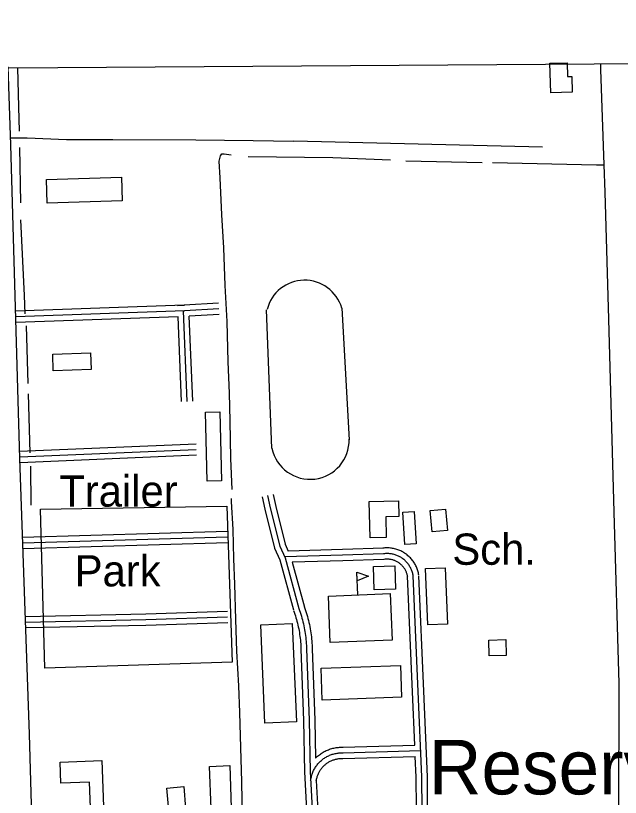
# Model space of a CAD drawing. Extents: x 3508733 to 3546731, y 546897 to 572481.
# Drawn here: x 3524097 to 3525704, y 568617 to 570695 of the extents above; entities that cross this region are included whole.
import ezdxf

# ---------------------------------------------------------------- set-up
doc = ezdxf.new("R2010")
doc.units = 0
for name, color, linetype in [('V-BLDG-IDEN', 7, 'Continuous'), ('V-BLDG-OTLN', 7, 'Continuous'), ('V-DTCH-CNTR', 7, 'Continuous'), ('V-GRID-FRAM', 7, 'Continuous'), ('V-ROAD-CNTR', 7, 'Continuous'), ('V-TOPO-GNAM-IDEN', 7, 'Continuous'), ('V-TOPO-SHOR', 7, 'Continuous')]:
    doc.layers.add(name, color=color, linetype=linetype)

msp = doc.modelspace()

# ---------------------------------------------------------------- linework, layer by layer
at = {"layer": 'V-BLDG-IDEN'}
msp.add_lwpolyline([(3524163, 569383.4), (3524658, 569391.5), (3524672.6, 568976.8), (3524174.1, 568960.4)], close=True, dxfattribs=at)
at = {"layer": 'V-BLDG-OTLN'}
for p, q in [((3525516.2, 570569), (3525562.5, 570569.3)), ((3525006.2, 569155.9), (3525003.7, 569215.9))]:
    msp.add_line(p, q, dxfattribs=at)
for points in [[(3525518.7, 570489.7), (3525516.2, 570569)], [(3525562.5, 570569.3), (3525563.6, 570533.3), (3525574.8, 570533.7), (3525576.1, 570491.5), (3525518.7, 570489.7)], [(3524778, 569545.1), (3524763.3, 569912.8)], [(3524963.5, 569917.9), (3524983, 569567.8)]]:
    msp.add_lwpolyline(points, dxfattribs=at)
for points in [[(3524379.8, 570203.1), (3524180.4, 570196.8), (3524178.4, 570259.5), (3524377.8, 570265.8)], [(3524297.4, 569754.5), (3524196.8, 569751.4), (3524195.4, 569795.5), (3524296, 569798.6)], [(3524639.5, 569641.7), (3524643.8, 569458.9), (3524605.7, 569458.1), (3524601.4, 569640.8)], [(3525038.7, 569307.2), (3525036.2, 569403.4), (3525114.4, 569405.5), (3525115.5, 569364.2), (3525080.4, 569363.3), (3525081.8, 569308.4)], [(3525155.8, 569377.4), (3525160.9, 569291.4), (3525130.9, 569289.6), (3525125.8, 569375.6)], [(3525203.3, 569323.3), (3525198.4, 569379.7), (3525239.4, 569383.3), (3525244.3, 569326.9)], [(3525106.4, 569170.8), (3525049.7, 569169), (3525047.7, 569231.2), (3525104.4, 569233)], [(3525192.2, 569076.1), (3525186.3, 569225.5), (3525238.6, 569227.6), (3525244.5, 569078.2)], [(3525003.7, 569215.9), (3525034.2, 569205.6), (3525004.7, 569192.8)], [(3525097.7, 569035.5), (3524933, 569028.7), (3524927.8, 569152.6), (3525092.5, 569159.5)], [(3524759.1, 568814.4), (3524748.2, 569076.4), (3524832, 569079.9), (3524842.9, 568817.9)], [(3525400.4, 568994.7), (3525355.4, 568993.2), (3525354, 569035.4), (3525399.1, 569036.8)], [(3525122.4, 568883.3), (3524911.4, 568875.7), (3524908.4, 568960.5), (3525119.3, 568968.1)], [(3524215.3, 568711.4), (3524326, 568715.4), (3524331.3, 568568.6), (3524296.7, 568567.4), (3524293.5, 568657.9), (3524217.3, 568655.1)], [(3524616.6, 568588), (3524612.4, 568699.7), (3524665.7, 568701.7), (3524669.9, 568590)], [(3524503.8, 568583.7), (3524498.5, 568642), (3524543.4, 568646), (3524548.6, 568587.8)]]:
    msp.add_lwpolyline(points, close=True, dxfattribs=at)
for centre, radius, start, end in [((3524864.8, 569889.2), 102.8, 16.2577, 165.9891), ((3524879.5, 569566.3), 103.6, 191.783, 1.8986)]:
    msp.add_arc(centre, radius, start, end, dxfattribs=at)
at = {"layer": 'V-DTCH-CNTR'}
msp.add_line((3525497.1, 570345.5), (3524836, 570361.2), dxfattribs=at)
msp.add_lwpolyline([(3524081.6, 570370.2), (3524127.3, 570369.9), (3524231.6, 570366.1), (3524355.4, 570366.3), (3524575.5, 570364.9), (3524727.8, 570362.8), (3524836, 570361.2)], dxfattribs=at)
at = {"layer": 'V-GRID-FRAM'}
msp.add_lwpolyline([(3512800, 570478.9), (3544431.3, 570695.1), (3544563.5, 552512.4), (3512916.4, 552296.1), (3512800, 570478.9)], dxfattribs=at)
at = {"layer": 'V-ROAD-CNTR'}
for points in [[(3524203.5, 566496.1), (3524208.2, 566552.7), (3524190.9, 567116.5), (3524174.8, 567625.9), (3524145.5, 568379.4), (3524133.2, 568785), (3524107.9, 569518.2), (3524083.6, 570351.6), (3524076.6, 570559.1)], [(3524636.3, 569930.6), (3524544.9, 569925.3), (3524096.4, 569909.9)], [(3524637.1, 569915.6), (3524545.6, 569910.3), (3524096.9, 569894.9)], [(3524527.1, 569924.7), (3524545.2, 569925.3)], [(3524552.7, 569670), (3524542.7, 569910.2), (3524545.6, 569910.3)], [(3524528.3, 569894.7), (3524097.4, 569879.9)], [(3524537.7, 569669.3), (3524528.3, 569894.7)], [(3524638, 569900.6), (3524558.3, 569896)], [(3524567.7, 569670.6), (3524558.3, 569896)], [(3524576.3, 569556.5), (3524107.2, 569536.6)], [(3524576.9, 569541.5), (3524107.8, 569521.6)], [(3524577.5, 569526.5), (3524108.5, 569506.6)], [(3524751.6, 569416.5), (3524758.7, 569383.5), (3524784.6, 569280.1), (3524799, 569248.7), (3524835.2, 569115.5)], [(3524766.2, 569419.6), (3524773.3, 569386.9), (3524798.9, 569285.1), (3524813.2, 569253.8), (3524849.7, 569119.4)], [(3524780.9, 569422.8), (3524787.9, 569390.3), (3524813.1, 569290.1), (3524821.3, 569272)], [(3524115.2, 569309.3), (3524659.6, 569324.9)], [(3524115.6, 569294.3), (3524660, 569309.9)], [(3524116.1, 569279.3), (3524660.4, 569294.9)], [(3525074.5, 569264.7), (3524965.5, 569261.3), (3524812.4, 569256.8), (3524813.2, 569253.8)], [(3525074, 569279.7), (3524965, 569276.3), (3524821.3, 569272)], [(3525168.2, 569208.4), (3525167.8, 569211), (3525167.2, 569213.8), (3525166.5, 569216.6), (3525165.8, 569219.3), (3525164.9, 569222.1), (3525164, 569224.8), (3525162.9, 569227.5), (3525161.8, 569230.1), (3525160.5, 569232.7), (3525159.2, 569235.3), (3525157.8, 569237.8), (3525156.4, 569240.3), (3525154.8, 569242.7), (3525153.1, 569245), (3525151.4, 569247.3), (3525149.6, 569249.6), (3525147.8, 569251.8), (3525145.8, 569253.9), (3525143.8, 569255.9), (3525141.7, 569257.9), (3525139.5, 569259.8), (3525137.3, 569261.7), (3525135.1, 569263.4), (3525132.7, 569265.1), (3525130.3, 569266.7), (3525127.9, 569268.2), (3525125.4, 569269.7), (3525122.9, 569271), (3525120.3, 569272.3), (3525117.7, 569273.5), (3525115, 569274.5), (3525112.3, 569275.5), (3525109.6, 569276.5), (3525106.8, 569277.3), (3525104, 569278), (3525101.2, 569278.6), (3525098.4, 569279.1), (3525095.6, 569279.6), (3525092.7, 569279.9), (3525089.8, 569280.2), (3525087, 569280.3), (3525084.1, 569280.4), (3525081.2, 569280.3), (3525078.3, 569280.2), (3525075.5, 569279.9), (3525072.7, 569279.6), (3525072.4, 569279.6)], [(3525153.5, 569205.8), (3525153.1, 569208.2), (3525152.6, 569210.5), (3525152, 569212.8), (3525151.4, 569215.1), (3525150.7, 569217.3), (3525149.9, 569219.6), (3525149, 569221.8), (3525148.1, 569224), (3525147.1, 569226.1), (3525146, 569228.2), (3525144.8, 569230.3), (3525143.6, 569232.3), (3525142.3, 569234.3), (3525141, 569236.3), (3525139.6, 569238.2), (3525138.1, 569240), (3525136.5, 569241.8), (3525134.9, 569243.5), (3525133.3, 569245.2), (3525131.6, 569246.9), (3525129.8, 569248.4), (3525128, 569249.9), (3525126.1, 569251.4), (3525124.2, 569252.8), (3525122.2, 569254.1), (3525120.2, 569255.4), (3525118.1, 569256.5), (3525116, 569257.7), (3525113.9, 569258.7), (3525111.7, 569259.7), (3525109.6, 569260.6), (3525107.3, 569261.4), (3525105.1, 569262.1), (3525102.8, 569262.8), (3525100.5, 569263.4), (3525098.2, 569263.9), (3525095.9, 569264.4), (3525093.5, 569264.7), (3525091.2, 569265), (3525088.8, 569265.2), (3525086.5, 569265.3), (3525084.1, 569265.4), (3525081.7, 569265.3), (3525079.3, 569265.2), (3525077, 569265), (3525074.6, 569264.7), (3525074.5, 569264.7)], [(3525075, 569249.7), (3524965.9, 569246.3), (3524831.8, 569242.3)], [(3524831.8, 569242.3), (3524864.1, 569123.3)], [(3525138.7, 569203.3), (3525138.3, 569205.4), (3525137.9, 569207.2), (3525137.5, 569209), (3525137, 569210.8), (3525136.4, 569212.6), (3525135.8, 569214.4), (3525135.1, 569216.1), (3525134.4, 569217.8), (3525133.6, 569219.5), (3525132.8, 569221.2), (3525131.9, 569222.8), (3525130.9, 569224.4), (3525129.9, 569225.9), (3525128.8, 569227.5), (3525127.7, 569229), (3525126.5, 569230.4), (3525125.3, 569231.8), (3525124.1, 569233.2), (3525122.8, 569234.5), (3525121.4, 569235.8), (3525120, 569237.1), (3525118.6, 569238.2), (3525117.1, 569239.4), (3525115.6, 569240.5), (3525114, 569241.5), (3525112.5, 569242.5), (3525110.8, 569243.4), (3525109.2, 569244.3), (3525107.5, 569245.1), (3525105.8, 569245.9), (3525104.1, 569246.6), (3525102.4, 569247.2), (3525100.6, 569247.8), (3525098.8, 569248.4), (3525097, 569248.8), (3525095.2, 569249.2), (3525093.4, 569249.6), (3525091.5, 569249.9), (3525089.7, 569250.1), (3525087.8, 569250.2), (3525085.9, 569250.3), (3525084.1, 569250.4), (3525082.2, 569250.3), (3525080.4, 569250.2), (3525078.5, 569250.1), (3525076.5, 569249.8), (3525076.5, 569249.8)], [(3525157.5, 568756.4), (3525151.8, 568898.2), (3525138.5, 569205.2)], [(3525177.8, 568494.3), (3525175.9, 568671.8), (3525166.8, 568898.8), (3525153.5, 569205.8)], [(3525192.6, 568510.3), (3525190.9, 568672.2), (3525181.8, 568899.4), (3525168.4, 569206.5)], [(3524849.7, 569119.4), (3524851.4, 569114.4), (3524853.1, 569109.4), (3524854.7, 569104.3), (3524856.2, 569099.2), (3524857.6, 569094.1), (3524859, 569089), (3524860.3, 569083.9), (3524861.5, 569078.7), (3524862.6, 569073.5), (3524863.7, 569068.3), (3524864.7, 569063.1), (3524865.6, 569057.9), (3524866.4, 569052.7), (3524867.1, 569047.4), (3524867.8, 569042.2), (3524868.4, 569036.9), (3524868.9, 569031.6), (3524869.3, 569026.3), (3524869.6, 569021), (3524869.9, 569015.7), (3524870, 569011.9)], [(3524863.8, 569124.3), (3524865.6, 569119.2), (3524867.4, 569114), (3524869, 569108.7), (3524870.6, 569103.4), (3524872.1, 569098.1), (3524873.5, 569092.8), (3524874.9, 569087.4), (3524876.1, 569082), (3524877.3, 569076.6), (3524878.4, 569071.2), (3524879.4, 569065.8), (3524880.4, 569060.3), (3524881.2, 569054.9), (3524882, 569049.4), (3524882.7, 569043.9), (3524883.3, 569038.4), (3524883.8, 569032.9), (3524884.2, 569027.4), (3524884.6, 569021.9), (3524884.9, 569016.4), (3524885, 569012.4)], [(3524122.6, 569098.5), (3524442.4, 569105.5), (3524659.8, 569111.9)], [(3524122.9, 569083.5), (3524442.8, 569090.5), (3524660.2, 569096.9)], [(3524835.5, 569114.5), (3524837.2, 569109.6), (3524838.8, 569104.7), (3524840.3, 569099.9), (3524841.8, 569095), (3524843.2, 569090.2), (3524844.5, 569085.3), (3524845.7, 569080.3), (3524846.9, 569075.4), (3524848, 569070.4), (3524849, 569065.5), (3524849.9, 569060.5), (3524850.8, 569055.5), (3524851.5, 569050.5), (3524852.3, 569045.4), (3524852.9, 569040.4), (3524853.4, 569035.4), (3524853.9, 569030.3), (3524854.3, 569025.2), (3524854.7, 569020.2), (3524854.9, 569015.1), (3524855, 569011.3)], [(3524123.2, 569068.5), (3524443.2, 569075.5), (3524660.7, 569081.9)], [(3524870, 569011.9), (3524876.5, 568822.2), (3524879.6, 568686), (3524890, 568486.5)], [(3524885, 569012.4), (3524891.5, 568822.6), (3524893.8, 568721.6)], [(3524855, 569011.4), (3524861.5, 568821.8), (3524864.6, 568685.5), (3524874.3, 568499.6)], [(3524893.8, 568721.6), (3524897.1, 568724.8), (3524899.4, 568726.9), (3524901.8, 568728.8), (3524904.1, 568730.7), (3524906.6, 568732.5), (3524909.1, 568734.2), (3524911.7, 568735.9), (3524914.3, 568737.5), (3524916.9, 568739), (3524919.7, 568740.4), (3524922.4, 568741.7), (3524925.2, 568743), (3524928, 568744.1), (3524930.9, 568745.2), (3524933.8, 568746.2), (3524936.7, 568747), (3524939.6, 568747.8), (3524942.6, 568748.5), (3524945.6, 568749.2), (3524948.6, 568749.7), (3524951.6, 568750.1), (3524954.6, 568750.4), (3524957.7, 568750.7), (3524960.7, 568750.8), (3524963.8, 568750.9), (3524966.7, 568750.8), (3524967.5, 568750.8)], [(3524966.6, 568750.8), (3525157.5, 568756.4)], [(3524967, 568735.8), (3525173.1, 568741.9)], [(3524880.8, 568661.9), (3524881.2, 568664.4), (3524881.6, 568667), (3524882.1, 568669.5), (3524882.7, 568672.1), (3524883.3, 568674.6), (3524884, 568677), (3524884.8, 568679.5), (3524885.7, 568681.9), (3524886.7, 568684.3), (3524887.7, 568686.7), (3524888.8, 568689), (3524890, 568691.4), (3524891.2, 568693.6), (3524892.6, 568695.8), (3524893.9, 568698), (3524895.4, 568700.2), (3524896.9, 568702.3), (3524898.5, 568704.3), (3524900.1, 568706.3), (3524901.8, 568708.3), (3524903.6, 568710.2), (3524905.4, 568712), (3524907.3, 568713.8), (3524909.2, 568715.5), (3524911.2, 568717.2), (3524913.2, 568718.8), (3524915.3, 568720.3), (3524917.4, 568721.8), (3524919.6, 568723.2), (3524921.8, 568724.5), (3524924.1, 568725.8), (3524926.4, 568727), (3524928.7, 568728.1), (3524931.1, 568729.2), (3524933.5, 568730.1), (3524935.9, 568731), (3524938.4, 568731.9), (3524940.8, 568732.6), (3524943.3, 568733.3), (3524945.8, 568733.9), (3524948.4, 568734.4), (3524950.9, 568734.9), (3524953.5, 568735.2), (3524956.1, 568735.5), (3524958.6, 568735.7), (3524961.2, 568735.8), (3524963.8, 568735.9), (3524966.4, 568735.9), (3524967, 568735.8)], [(3524966.5, 568720.8), (3525158.7, 568726.4)], [(3525162.6, 568508.4), (3525160.9, 568671.5), (3525158.7, 568726.4)], [(3524895.8, 568662.3), (3524897.2, 568668.5), (3524897.8, 568670.5), (3524898.4, 568672.6), (3524899, 568674.6), (3524899.8, 568676.6), (3524900.5, 568678.6), (3524901.4, 568680.5), (3524902.3, 568682.4), (3524903.3, 568684.3), (3524904.3, 568686.2), (3524905.4, 568688), (3524906.5, 568689.8), (3524907.7, 568691.6), (3524908.9, 568693.3), (3524910.2, 568695), (3524911.6, 568696.6), (3524913, 568698.2), (3524914.4, 568699.8), (3524915.9, 568701.3), (3524917.4, 568702.7), (3524919, 568704.2), (3524920.7, 568705.5), (3524922.3, 568706.8), (3524924, 568708.1), (3524925.8, 568709.3), (3524927.6, 568710.5), (3524929.4, 568711.6), (3524931.2, 568712.6), (3524933.1, 568713.6), (3524935, 568714.5), (3524937, 568715.4), (3524938.9, 568716.2), (3524940.9, 568716.9), (3524942.9, 568717.6), (3524945, 568718.2), (3524947, 568718.8), (3524949.1, 568719.3), (3524951.2, 568719.7), (3524953.3, 568720), (3524955.4, 568720.3), (3524957.5, 568720.6), (3524959.6, 568720.7), (3524961.7, 568720.8), (3524963.8, 568720.9), (3524966, 568720.9), (3524966.5, 568720.8)], [(3524895.8, 568662.3), (3524904.1, 568503.2)]]:
    msp.add_lwpolyline(points, dxfattribs=at)
at = {"layer": 'V-TOPO-SHOR'}
for p, q in [((3524106.8, 570344.5), (3524109.3, 570197.5)), ((3525133.9, 570309.3), (3525336.3, 570304.6)), ((3524124.5, 569871.1), (3524128.9, 569717.6)), ((3524129.8, 569689.6), (3524134.8, 569533.1)), ((3524135.9, 569497.3), (3524137, 569393.9))]:
    msp.add_line(p, q, dxfattribs=at)
for points in [[(3524101.5, 570556.1), (3524104.7, 570452.8), (3524106.4, 570388.1)], [(3525699.7, 568563.9), (3525701.1, 568920.4), (3525687.8, 569375.2), (3525673.4, 569888), (3525663.4, 570225.7), (3525660.9, 570298.2), (3525652.1, 570552), (3525651.6, 570566.7)], [(3524672.6, 569435.6), (3524668.8, 569518.3), (3524666.7, 569618.4), (3524664.7, 569691.7), (3524661.9, 569775.4), (3524658.9, 569881.9), (3524653.8, 569977.5), (3524649.7, 570077.6), (3524645, 570165.3), (3524640.4, 570263.8), (3524638, 570307.9), (3524641.2, 570322.8), (3524645.2, 570327.7), (3524651.2, 570328.1), (3524670, 570324.8)], [(3524714.9, 570320.6), (3524939.8, 570318.4), (3525092.8, 570312)], [(3525363.9, 570304.5), (3525640.9, 570298.3), (3525660.9, 570298.2)], [(3524109.9, 570152.6), (3524119.2, 569950.9), (3524121.1, 569902.4)], [(3524703.7, 568499.4), (3524700.1, 568560.8), (3524698, 568658.4), (3524695.3, 568750), (3524692.6, 568842.6), (3524690.1, 568913.5), (3524684.5, 569005.6), (3524681.7, 569089.9), (3524679.5, 569184), (3524677, 569251.3), (3524674.6, 569329.6), (3524670.6, 569403.4), (3524670.3, 569411.8)]]:
    msp.add_lwpolyline(points, dxfattribs=at)

# ---------------------------------------------------------------- texts
at = {"layer": 'V-BLDG-IDEN'}
for s, p in [('Trailer ', (3524212.8, 569390.1)), ('Sch.', (3525257.4, 569235.6)), ('Park', (3524253.8, 569178.1))]:
    msp.add_text(s, height=83, dxfattribs=at).set_placement(p)
at = {"layer": 'V-TOPO-GNAM-IDEN'}
msp.add_text('Reserve', height=145, dxfattribs=at).set_placement((3525194.8, 568625.3))

doc.saveas('drawing.dxf')
